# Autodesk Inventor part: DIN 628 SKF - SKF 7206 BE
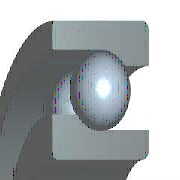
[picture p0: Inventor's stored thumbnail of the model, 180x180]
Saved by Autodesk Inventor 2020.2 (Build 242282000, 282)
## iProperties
Manager: www.cadconsulting.pl
Company: Fabian Stasiak CAD Consulting
Created: 2010-02
Part Number: DIN 628 SKF - SKF 7206 BE
Material: Stal, miękka
Description: Łożyska toczne kulkowe skośne jednorzędowe SKF
Document SubType Name: Modeling
Standard: DIN 628 SKF
Designer: F.Stasiak
Standards Organization: DIN
Language: pl-PL
Size Designation: SKF 7206 BE
Categories: <MemberInstance><Categories><Category DisplayName="Części wałów" InternalName="7f7aeb1f-a693-4053-b835-cee3144e0d98" Mnemonic="SHFT"><Category DisplayName="Łoży
Density: 7.86 g/cm^3
Appearance: Metal-Stal
IsCustomPart: 0
Author: F.Stasiak
Subject: Zbiór ćwiczeń. Autodesk Inventor 2020. Kurs podstawowy
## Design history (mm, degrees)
node "WorkPlane1"
workplane "Work Plane2"
node "WorkPlane2"
node "Sketch1"
node "WorkPoint1"
node "Sketch2"
node "WorkPoint3"
node "Sketch3"
node "WorkPoint2"
sketch "Sketch4"
  geometry: L1 (31, 0)-(15, 0); L2 (31, 16)-(31, 0); L3 (15, 16)-(31, 16); L4 (15, 0)-(15, 16); L5 (0, -3.737)-(0, 15.931); L6 (0, -3.737)-(0, 15.931); L7 (0, -7.671)-(0, 19.865) reference; L8 (-4.7, 0)-(28.2, 0) reference
  constraints: 12 end point, 3 vertical, 2 collinear, 2 horizontal
  dimensions: "d2" = 15 horizontal distance of L3.start L5.end (= 0.5 x Diam); "d4" = 31 horizontal distance of L2.start L5.end (= 0.5 x DD); "d6" = 16 distance of L1.end L3.start (= B)
revolve "Revolution1" sketch "Sketch4" stored, may be unused: angle "d7" = 360 deg
node "WorkAxis1"
sketch "Sketch5"
  geometry: L1 (27.8, 16)-(20.12, 16); L2 (27.8, 8)-(27.8, 16); L3 (25.88, 0)-(25.88, 4.16); L4 (18.2, 0)-(25.88, 0); L5 (18.2, 8)-(18.2, 0); L6 (20.12, 16)-(20.12, 11.84); L7 (31, 0)-(-31, 0) reference; L8 (31, 16)-(-31, 16) reference; L9 (0, 40.963)-(0, -26.963); L10 (0, -40.549)-(0, 54.549) reference; A1 r 4.8 centre (23, 8) between (25.88, 4.16) and (27.8, 8); A2 r 4.8 centre (23, 8) between (20.12, 11.84) and (18.2, 8); A3 r 4.8 centre (23, 8) between (27.8, 8) and (20.12, 11.84)
  constraints: 14 end point, 7 point on circle, 4 vertical, 3 centre point, 3 collinear, 2 horizontal, 2 tangent, 1 coincident, 1 concentric
  dimensions: "d9" = 8 vertical distance of A2.centre L3.start (= 0.5 x B); "d11" = 9.6 diameter of A3 (= msp_mdtdk); "d21" = 46 diameter of A1.centre L9 (= msp_mdtds); "d22" = 40.24 diameter of L6 L9 (= msp_md); "d23" = 51.76 diameter of L3 L9 (= msp_vd)
revolve "Revolution2" sketch "Sketch5" stored, may be unused: angle "d12" = 360 deg
sketch "Sketch6"
  geometry: L1 (23, 3.2)-(23, 12.8); L2 (23, 16.175)-(23, -0.013); L3 (31, 0)-(-31, 0) reference; L4 (23, 16.175)-(23, -0.013); L5 (27.8, 8)-(-27.8, 8) reference; A1 r 4.8 centre (23, 8) between (23, 3.2) and (23, 12.8); A2 r 4.8 centre (23, 8) between (20.12, 11.84) and (18.2, 8) reference
  constraints: 6 end point, 4 point on line, 2 point on circle, 1 centre point, 1 concentric, 1 vertical
  dimensions: "d14" = 4.8 radius of A1 (= 0.5 x msp_mdtdk)
revolve "Revolution3" sketch "Sketch6" stored, may be unused: angle "d15" = 360 deg
workaxis "Work Axis2"
pattern_circular "PolarArray1" dims angle "d18" = 360 deg
fillet "Fillet1" dims "d19" = 0.6 (= r1)
fillet "Fillet2" dims "d20" = 1 (= r)
body "Solid1"
node "Sketch7"
other parameters: "DD" = 62 [user parameter; used in 3 equation terms], "B" = 16 [user parameter; used in 3 equation terms], "r" = 1 [user parameter; used in 1 equation term], "msp_mdtdk" = 9.6 (= -0.3 x Diam + 0.3 x DD) [user parameter; used in 5 equation terms], "msp_mdtds" = 46 (= 0.5 x DD + 0.5 x Diam) [user parameter; used in 4 equation terms], "msp_md" = 40.24 (= msp_mdtds - 0.6 x msp_mdtdk) [user parameter; used in 1 equation term], "msp_vd" = 51.76 (= msp_mdtds + 0.6 x msp_mdtdk) [user parameter; used in 1 equation term], "r1" = 0.6 [user parameter; used in 1 equation term], "d0" = -16 (computed from B), "d3" = 23.5 (derived), "d5" = 14 (derived), "d8" = 7 (derived), "d10" = 8.1 (derived), "d13" = 4.05 (derived), "d26" = 0, "d27" = 0, "d28" = 0, "d29" = 0, "d30" = 0
